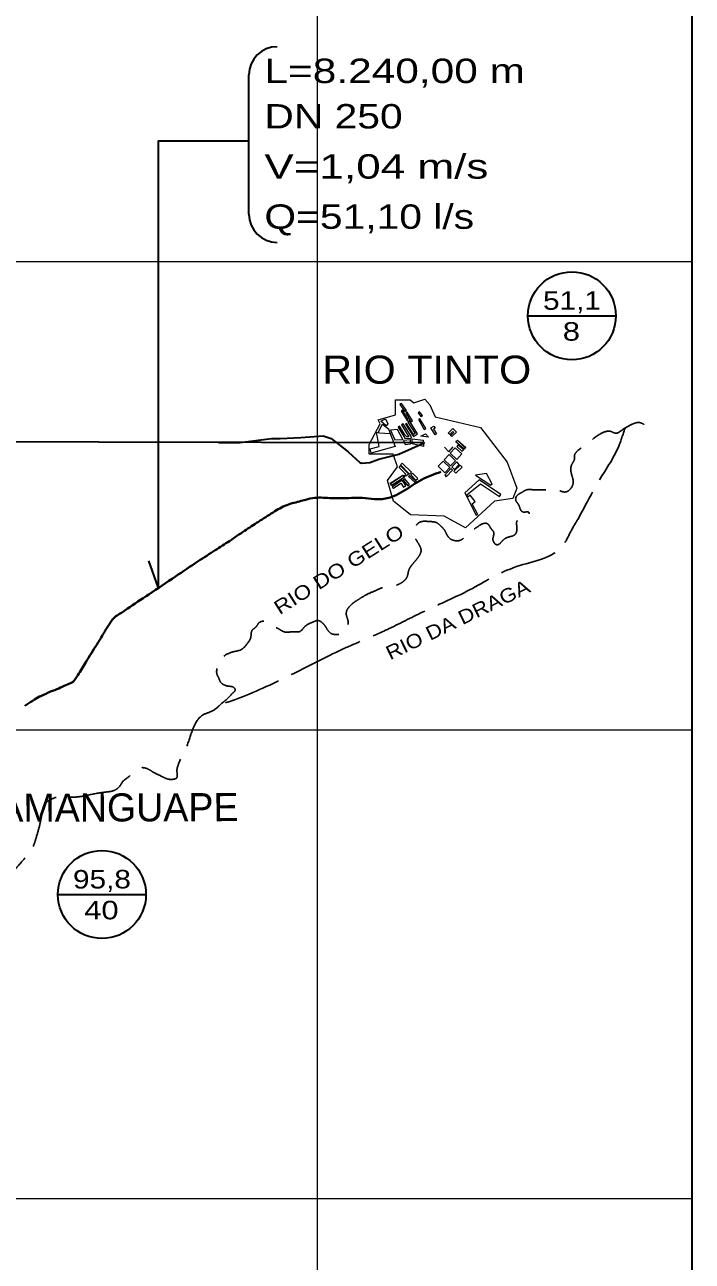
# Model space of a CAD drawing. Extents: x 0 to 1772, y 0 to 1188.
# Drawn here: x 1085.1 to 1175.9, y 181.7 to 349.8 of the extents above; entities that cross this region are included whole.
import ezdxf
from ezdxf.enums import TextEntityAlignment as Align

# ---------------------------------------------------------------- set-up
doc = ezdxf.new("R2010")
doc.units = 0
doc.header["$LTSCALE"] = 1.3
doc.linetypes.add('DOT_DASHED', pattern=[7.7, 5, -1.2, 0.3, -1.2])
doc.linetypes.add('LONG_DASHED', pattern=[7.5, 6, -1.5])
for name, color, linetype, lineweight in [('1', 7, 'DOT_DASHED', 13), ('3', 7, 'Continuous', 35), ('5', 7, 'LONG_DASHED', 25), ('6', 7, 'Continuous', 40), ('63', 7, 'Continuous', 25), ('8', 7, 'Continuous', 35), ('9', 7, 'Continuous', 40)]:
    doc.layers.add(name, color=color, linetype=linetype, lineweight=lineweight)

msp = doc.modelspace()

# ---------------------------------------------------------------- linework, layer by layer
at = {"layer": '1', "linetype": 'Continuous'}
msp.add_line((1148.701, 287.361), (1148.494, 287.187), dxfattribs=at)
for points in [[(1151.489, 285.394), (1148.987, 285.048), (1145.041, 281.413), (1142.161, 282.996), (1137.56, 283.152), (1135.254, 285.041), (1134.468, 287.849), (1135.816, 289.716), (1135.202, 291.407), (1131.954, 291.431), (1131.964, 292.717), (1133.464, 295.533), (1133.192, 296.108), (1135.524, 296.792), (1135.518, 298.79), (1137.516, 298.796), (1138.056, 298.391), (1139.543, 298.903), (1140.222, 298.127), (1140.222, 298.127), (1140.937, 296.503), (1147.097, 295.066), (1150.73, 290.336), (1152.06, 286.784)], [(1136.14, 298.169), (1136.822, 297.225), (1137.029, 297.375), (1136.348, 298.319)], [(1133.534, 295.9), (1134.182, 296.212), (1134.495, 295.563), (1134.259, 295.281)], [(1136.305, 297.312), (1137.106, 295.984), (1137.275, 296.086), (1136.474, 297.414)], [(1136.941, 297.033), (1137.623, 295.838), (1137.83, 295.956), (1137.147, 297.151)], [(1138.624, 297.053), (1138.994, 296.537), (1139.198, 296.683), (1138.827, 297.199)], [(1138.671, 296.122), (1139.457, 294.779), (1139.65, 294.892), (1138.863, 296.235)], [(1132.232, 291.565), (1132.083, 292.126), (1133.329, 292.458), (1132.977, 294.42), (1133.361, 294.317), (1134.823, 294.248), (1135.478, 292.476)], [(1134.881, 294.677), (1135.431, 293.378), (1136.538, 293.44), (1135.81, 294.798)], [(1137.718, 293.769), (1136.605, 295.569), (1136.355, 295.414), (1137.359, 293.791), (1137.083, 293.796), (1136.861, 294.003), (1136.09, 295.212), (1135.883, 295.08), (1136.82, 293.61), (1137.645, 293.576)], [(1137.446, 295.956), (1137.24, 295.778), (1138.219, 294.228), (1138.004, 294.093), (1137.054, 295.597), (1136.907, 295.504), (1137.967, 293.826), (1138.511, 294.169)], [(1140.916, 294.067), (1140.34, 294.991), (1140.758, 295.251), (1140.929, 294.977), (1140.712, 294.842), (1141.126, 294.177)], [(1143.21, 293.811), (1143.044, 293.976), (1143.453, 294.387), (1143.339, 294.5), (1142.918, 294.077), (1142.719, 294.275), (1143.342, 294.9), (1143.847, 294.397)], [(1136.612, 293.263), (1136.865, 292.732), (1137.632, 292.808), (1137.576, 293.373)], [(1139.331, 292.488), (1137.81, 292.808), (1137.793, 293.518), (1139.284, 293.315)], [(1140.022, 293.717), (1138.973, 293.861), (1139.636, 294.188)], [(1144.889, 292.117), (1143.759, 293.108), (1143.96, 293.338), (1145.09, 292.346)], [(1144.846, 292.104), (1143.766, 293.147), (1143.955, 293.342), (1145.035, 292.299)], [(1143.878, 292.482), (1144.577, 291.818), (1144.771, 292.023), (1144.073, 292.687)], [(1142.154, 290.659), (1143.041, 289.815), (1143.723, 290.533), (1142.836, 291.376)], [(1143.884, 290.711), (1142.958, 291.539), (1143.636, 292.298), (1144.562, 291.47)], [(1136.937, 288.416), (1136.789, 288.563), (1136.936, 288.711), (1136.025, 289.618), (1136.239, 289.833), (1137.357, 288.72)], [(1137.706, 288.96), (1136.454, 290.206), (1136.212, 289.962), (1137.464, 288.717)], [(1142.93, 289.606), (1142.004, 290.484), (1141.337, 289.78), (1142.262, 288.902)], [(1143.067, 289.469), (1142.233, 288.55), (1142.455, 288.349), (1143.289, 289.268)], [(1143.551, 289.331), (1144.222, 290.015), (1143.866, 290.364), (1143.195, 289.68)], [(1144.591, 289.663), (1143.756, 288.838), (1143.49, 289.107), (1144.325, 289.932)], [(1134.833, 287.494), (1136.529, 288.575), (1136.73, 288.258), (1135.008, 287.16)], [(1134.858, 287.419), (1136.582, 288.563), (1136.768, 288.282), (1135.044, 287.139)], [(1135.259, 286.785), (1136.275, 287.483), (1136.642, 286.948), (1136.957, 287.164), (1136.462, 287.886), (1135.105, 286.955)], [(1136.584, 287.883), (1137.236, 287.101), (1137.444, 287.275), (1136.792, 288.056)], [(1138.209, 287.548), (1137.306, 288.387), (1137.44, 288.532), (1138.343, 287.692)], [(1137.615, 288.595), (1138.326, 287.873), (1138.558, 288.101), (1137.847, 288.823)]]:
    msp.add_lwpolyline(points, close=True, dxfattribs=at)
for points in [[(1133.187, 294.364), (1133.786, 295.486), (1134.57, 294.853), (1134.823, 294.248)], [(1142.205, 292.356), (1142.796, 291.74), (1143.383, 292.398)], [(1149.877, 285.931), (1146.934, 287.917), (1144.973, 286.152), (1146.502, 283.112), (1146.754, 283.238), (1145.973, 284.685)], [(1148.701, 287.361), (1147.934, 288.782), (1146.41, 288.569), (1146.41, 288.569), (1147.452, 287.878), (1148.494, 287.187), (1148.494, 287.187)], [(1145.973, 284.685), (1146.366, 285.001), (1145.692, 285.837), (1145.438, 285.633), (1145.233, 285.887), (1147.112, 287.401), (1149.694, 285.668), (1149.877, 285.931)]]:
    msp.add_lwpolyline(points, dxfattribs=at)
at = {"layer": '3'}
msp.add_lwpolyline([(1111.478, 293.024), (1114.361, 293.024), (1118.67, 293.553), (1119.855, 293.564), (1122.656, 293.686), (1125.705, 293.926), (1126.796, 293.572), (1129.091, 291.75), (1130.689, 290.288), (1130.964, 290.185), (1132.028, 290.298), (1133.265, 290.737), (1135.978, 291.442), (1139.418, 292.958), (1006.614, 293.247)], dxfattribs=at)
msp.add_lwpolyline([(1111.478, 293.024), (1114.361, 293.024), (1118.67, 293.553), (1119.855, 293.564), (1122.656, 293.686), (1125.705, 293.926), (1126.796, 293.572), (1129.091, 291.75), (1130.689, 290.288), (1130.964, 290.185), (1132.028, 290.298), (1133.265, 290.737), (1135.978, 291.442), (1139.418, 292.958), (1006.614, 293.247)], dxfattribs=at)
at = {"layer": '5'}
for points in [[(1166.722, 294.919), (1165.914, 292.512), (1163.067, 287.56), (1160.332, 282.552), (1159.272, 280.696), (1158.379, 279.064), (1151.991, 276.124), (1145.604, 272.959), (1139.608, 270.133), (1134.678, 267.703), (1130.755, 265.95), (1128.34, 264.915)], [(1169.345, 295.468), (1168.649, 295.733), (1167.733, 295.493), (1166.42, 294.749), (1165.475, 294.273), (1164.853, 294.508), (1163.597, 294.282), (1161.93, 293.122), (1160.396, 291.949), (1159.88, 291.237), (1159.882, 290.763), (1159.5, 289.977), (1159.504, 288.645), (1159.714, 287.521), (1159.214, 286.572), (1158.83, 286.319), (1157.732, 286.506), (1157.063, 286.713), (1156.483, 286.579), (1155.607, 286.577), (1154.446, 286.573), (1153.373, 286.57), (1152.673, 286.195), (1152.192, 285.898), (1151.941, 285.59), (1151.943, 285.042), (1152.24, 284.626), (1152.45, 284.134), (1152.725, 283.641), (1153.054, 283.532), (1153.656, 283.534), (1153.657, 283.14), (1153.285, 283.029), (1152.749, 282.907), (1152.312, 282.598), (1152.039, 282.258), (1152.041, 281.567), (1152.043, 281.041), (1151.869, 280.558), (1151.333, 280.249)], [(1151.333, 280.249), (1150.459, 279.957), (1149.874, 279.405), (1149.533, 279.135), (1149.216, 279.134), (1148.934, 279.427), (1148.787, 279.793), (1148.918, 280.796), (1148.587, 281.235), (1148.329, 281.637), (1148.06, 281.954), (1147.385, 281.952), (1146.503, 281.419), (1145.799, 280.993), (1145.331, 280.531), (1144.844, 280.031), (1144.356, 279.709), (1143.425, 279.707), (1142.945, 279.94), (1142.596, 280.353), (1142.275, 280.983), (1141.718, 281.64), (1141.108, 282.108), (1140.079, 282.269), (1139.129, 282.266), (1138.601, 282.014), (1138.238, 281.47), (1138.119, 280.618), (1138.293, 279.875), (1138.795, 279.054), (1139.019, 278.311), (1138.864, 277.774), (1138.387, 277.1), (1138.002, 276.627), (1137.585, 276.11), (1137.314, 275.535), (1137.165, 274.871), (1136.888, 274.374), (1136.461, 274.016), (1135.877, 273.679), (1134.959, 273.454), (1133.79, 273.278), (1132.779, 272.85), (1131.473, 272.257), (1130.686, 271.777), (1129.874, 271.238), (1129.097, 270.49), (1128.839, 269.813), (1129.085, 268.722), (1128.846, 267.629), (1128.328, 267.09), (1127.601, 266.88), (1126.665, 267.119), (1126.057, 267.932)], [(1126.103, 267.871), (1125.533, 268.528), (1124.993, 268.791), (1124.277, 268.583), (1123.269, 268.05), (1122.448, 267.272), (1121.771, 267.27), (1120.369, 267.266), (1119.76, 267.598), (1119.073, 267.978), (1118.447, 268.483), (1116.945, 268.478), (1116.604, 267.973), (1116.031, 267.466), (1115.862, 266.547), (1115.27, 265.526), (1114.416, 264.777), (1113.674, 264.596), (1112.803, 264.308), (1111.905, 263.699), (1111.512, 262.981), (1111.276, 262.328), (1111.278, 261.418), (1111.482, 261.023), (1111.657, 260.564), (1111.971, 260.188), (1112.44, 259.96), (1112.899, 259.86), (1113.496, 259.724), (1113.736, 259.348), (1113.416, 258.952), (1112.702, 258.196), (1111.814, 257.449)], [(1128.333, 264.921), (1121.156, 261.341), (1113.766, 258.071), (1111.723, 257.376)], [(1111.814, 257.449), (1110.661, 256.529), (1109.273, 255.911), (1108.052, 254.233), (1107.187, 251.8), (1106.064, 249.391), (1105.808, 248.258), (1105.81, 247.479), (1104.585, 247.24), (1103.712, 247.614), (1102.58, 248.177), (1102.037, 248.506), (1101.046, 248.786), (1099.823, 248.027), (1098.436, 246.938)], [(1098.436, 246.938), (1097.807, 246.034), (1097.288, 245.694), (1096.079, 245.469), (1093.569, 245.019), (1092.282, 244.807), (1090.825, 244.802), (1089.615, 244.799), (1088.498, 244.379), (1087.889, 243.934), (1087.489, 242.825), (1087.147, 241.019), (1086.658, 239.259), (1086.205, 237.957), (1085.595, 237.012), (1084.774, 236.085), (1083.091, 234.22), (1082.101, 233.196), (1081.312, 232.334), (1080.641, 232.332), (1079.69, 231.779), (1078.793, 231.118), (1077.761, 230.712), (1077.198, 230.32), (1077.038, 230.038)]]:
    msp.add_spline(points, degree=3, dxfattribs=at)
at = {"layer": '6'}
msp.add_spline([(1141.703, 289.017), (1139.09, 287.947), (1136.572, 286.38), (1135.288, 285.72), (1134.631, 285.487), (1133.75, 285.311), (1132.664, 285.307), (1131.034, 285.471), (1129.541, 285.466), (1126.573, 285.457), (1124.264, 285.451), (1122.711, 285.061), (1120.737, 284.501), (1118.882, 283.512), (1116.882, 282.22), (1115.002, 280.992), (1112.95, 279.613), (1111.028, 278.365), (1108.694, 276.854), (1105.596, 274.787), (1101.97, 272.351), (1099.021, 270.37), (1097.999, 269.691), (1097.344, 269.258), (1096.996, 268.881), (1096.618, 268.321), (1096.137, 267.562), (1095.849, 267.065), (1094.947, 265.6), (1093.399, 263.116), (1092.316, 261.373), (1091.951, 260.831), (1091.796, 260.576), (1091.526, 260.378), (1090.697, 260.014), (1089.732, 259.556), (1088.624, 259.132), (1087.804, 258.757), (1087.117, 258.451), (1086.235, 257.906), (1085.656, 257.537), (1085.102, 257.182)], degree=3, dxfattribs=at)
at = {"layer": '63', "lineweight": 13}
for p, q in [((1124.943, 62.735), (1124.943, 419.523)), ((1175.913, 317.583), (487.822, 317.583)), ((1175.913, 253.871), (487.822, 253.871)), ((1175.913, 190.159), (487.822, 190.159))]:
    msp.add_line(p, q, dxfattribs=at)
at = {"layer": '63', "lineweight": 35}
msp.add_line((1175.913, 62.735), (1175.913, 419.523), dxfattribs=at)
at = {"layer": '8'}
msp.add_line((1115.605, 324.054), (1115.605, 343.01), dxfattribs=at)
msp.add_lwpolyline([(1115.605, 334.011), (1103.255, 334.011), (1103.255, 273.353), (1101.989, 276.919)], dxfattribs=at)
for centre, start, end in [((1119.427, 343.01), 90, 180), ((1119.427, 343.01), 90, 180), ((1119.427, 343.01), 90, 180), ((1119.427, 324.054), 180, 270)]:
    msp.add_arc(centre, 3.823, start, end, dxfattribs=at)
at = {"layer": '9', "lineweight": 35}
for p, q in [((1153.55, 310.242), (1165.52, 310.242)), ((1089.613, 231.537), (1101.584, 231.537))]:
    msp.add_line(p, q, dxfattribs=at)
for centre in [(1159.535, 310.242), (1095.599, 231.537)]:
    msp.add_circle(centre, 5.985, dxfattribs=at)

# ---------------------------------------------------------------- texts
at = {"layer": '5'}
for s, rotation, width, p in [('RIO DO GELO', 32.342, 1.2, (1119.778, 269.52)), ('RIO DA DRAGA', 25.978, 1.15, (1134.819, 263.37))]:
    msp.add_text(s, height=1.911, rotation=rotation, dxfattribs=dict(at, width=width)).set_placement(p)
at = {"layer": '8'}
for s, width, p in [('L=8.240,00 m', 1.3, (1117.702, 341.896)), ('DN 250', 1.25, (1117.702, 335.717)), ('V=1,04 m/s', 1.35, (1117.702, 328.893)), ('Q=51,10 l/s', 1.25, (1117.702, 322.069))]:
    msp.add_text(s, height=3.319, dxfattribs=dict(at, width=width)).set_placement(p)
at = {"layer": '9'}
for s, width, p in [('51,1', 1.2, (1159.545, 311.062)), ('8', 1.25, (1159.471, 306.859)), ('95,8', 1.2, (1095.608, 232.357)), ('40', 1.25, (1095.534, 228.154))]:
    msp.add_text(s, height=2.52, rotation=0.17, dxfattribs=dict(at, width=width)).set_placement(p, align=Align.CENTER)
at = {"layer": '9', "width": 1.1}
msp.add_text('RIO TINTO', height=3.823, dxfattribs=at).set_placement((1125.577, 301.005))
at = {"layer": '9'}
msp.add_text('MAMANGUAPE', height=3.823, rotation=0.17, dxfattribs=at).set_placement((1077.26, 241.408))

doc.saveas('drawing.dxf')
